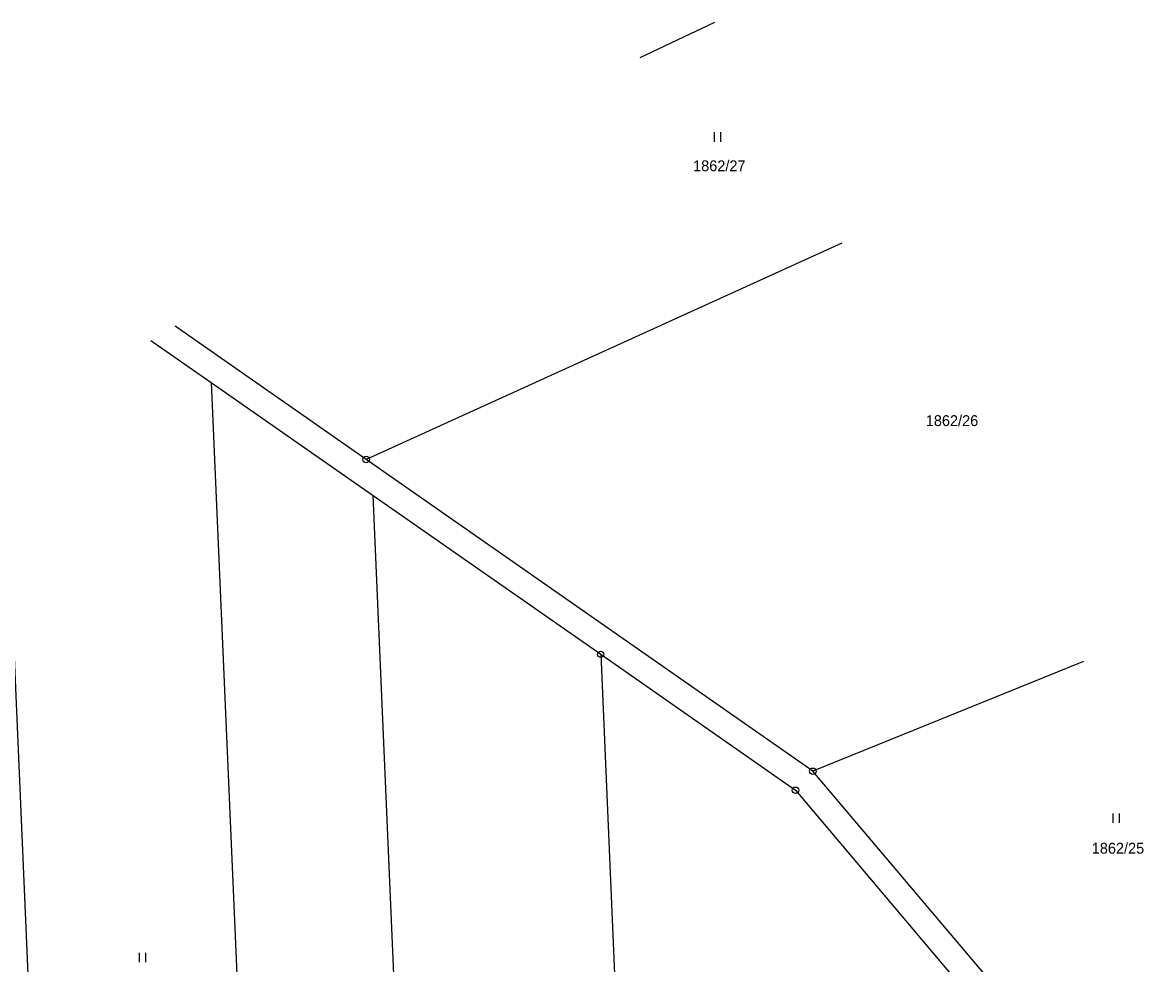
# Model space of a CAD drawing. Extents: x -758836 to -757729, y -1175316 to -1174366.
# Drawn here: x -758099.9 to -757924.1, y -1174513.4 to -1174365.7 of the extents above; entities that cross this region are included whole.
import ezdxf

# ---------------------------------------------------------------- set-up
doc = ezdxf.new("R2010")
doc.units = 0
for name, color, linetype in [('Hranice parcel', 7, 'Continuous'), ('Parcelní čísla', 7, 'Continuous'), ('Značky bodu BP', 7, 'Continuous'), ('Značky kultur', 7, 'Continuous')]:
    doc.layers.add(name, color=color, linetype=linetype)

msp = doc.modelspace()

# ---------------------------------------------------------------- linework, layer by layer
at = {"layer": 'Hranice parcel'}
for p, q in [((-757991.41, -1174365.74), (-758003.07, -1174371.31)), ((-757971.45, -1174400.31), (-758045.98, -1174434.24)), ((-758045.98, -1174434.24), (-758075.9, -1174413.36)), ((-758070.27, -1174422.16), (-758044.88, -1174439.88)), ((-758070.27, -1174422.16), (-758062.75, -1174595)), ((-758094.97, -1174606.08), (-758102.68, -1174428.83)), ((-757975.97, -1174483.1), (-758045.98, -1174434.24)), ((-758044.88, -1174439.88), (-758009.22, -1174464.77)), ((-758038.54, -1174585.88), (-758044.88, -1174439.88)), ((-758009.22, -1174464.77), (-758004.53, -1174572.62)), ((-757933.57, -1174465.91), (-757975.97, -1174483.1)), ((-757939.23, -1174526.49), (-757975.97, -1174483.1))]:
    msp.add_line(p, q, dxfattribs=at)
for points in [[(-758079.72, -1174415.57), (-758070.27, -1174422.16)], [(-758009.22, -1174464.77), (-757978.69, -1174486.08), (-757937.94, -1174534.35), (-757938.59, -1174546.91)]]:
    msp.add_lwpolyline(points, dxfattribs=at)
at = {"layer": 'Značky bodu BP'}
for centre, radius in [((-758045.98, -1174434.24), 0.5), ((-758045.98, -1174434.24), 0.0303), ((-758009.22, -1174464.77), 0.5), ((-758009.22, -1174464.77), 0.0303), ((-757975.97, -1174483.1), 0.5), ((-757975.97, -1174483.1), 0.0303), ((-757978.69, -1174486.08), 0.5), ((-757978.69, -1174486.08), 0.0303)]:
    msp.add_circle(centre, radius, dxfattribs=at)
at = {"layer": 'Značky kultur'}
for p, q in [((-757991.4, -1174384.45), (-757991.4, -1174382.95)), ((-757990.4, -1174384.45), (-757990.4, -1174382.95)), ((-757928.91, -1174491.2), (-757928.91, -1174489.7)), ((-757927.91, -1174491.2), (-757927.91, -1174489.7)), ((-758081.51, -1174513.04), (-758081.51, -1174511.54)), ((-758080.51, -1174513.04), (-758080.51, -1174511.54))]:
    msp.add_line(p, q, dxfattribs=at)

# ---------------------------------------------------------------- texts
at = {"layer": 'Parcelní čísla'}
for s, p in [('1862/27', (-757994.74, -1174389.06)), ('1862/26', (-757958.27, -1174429)), ('1862/25', (-757932.26, -1174496.02))]:
    msp.add_text(s, height=1.7, dxfattribs=at).set_placement(p)

doc.saveas('drawing.dxf')
